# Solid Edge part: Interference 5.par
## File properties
Last saved by: Lee
Revision: 59
Accuracy: 0.990
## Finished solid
Body 1: solid body, 5 faces, 6 edges, 2 vertices.
  Faces by surface: cylinder 4, plane 1
  Edges by curve: intersection 4, circle 1, ellipse 1
Bounding box of the edges (mm): 101.268 x 219.084 x 304.859, from (-809.8183, -383.5428, 251.9719) to (-708.5504, -164.4586, 556.8306).
Cylindrical faces by radius (mm): R91 x1, R109.5375 x1, R850 x1, R875.4 x1
Planar faces by outward normal: oblique 1
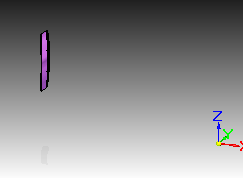
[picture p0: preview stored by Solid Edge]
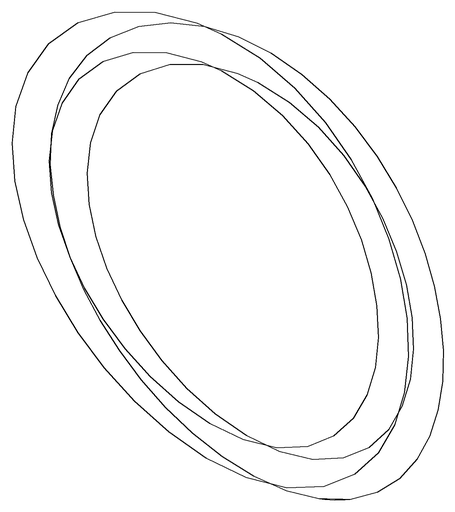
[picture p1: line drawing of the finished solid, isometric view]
